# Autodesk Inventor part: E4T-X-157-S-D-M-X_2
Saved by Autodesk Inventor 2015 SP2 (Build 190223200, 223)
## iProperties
Created: 2016-05
Part Number: E4T-X-157-S-D-M-X_2
Material: Allgemein
Document SubType Name: Modeling
Designer: ryll
Density: 1 g/cm^3
Appearance: Vorgabe
Author: ryll
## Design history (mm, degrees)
node "E4T-X-157-S-D-M-X_21"
node "E4T-X-157-S-D-M-X_2"
node "Basis1"
